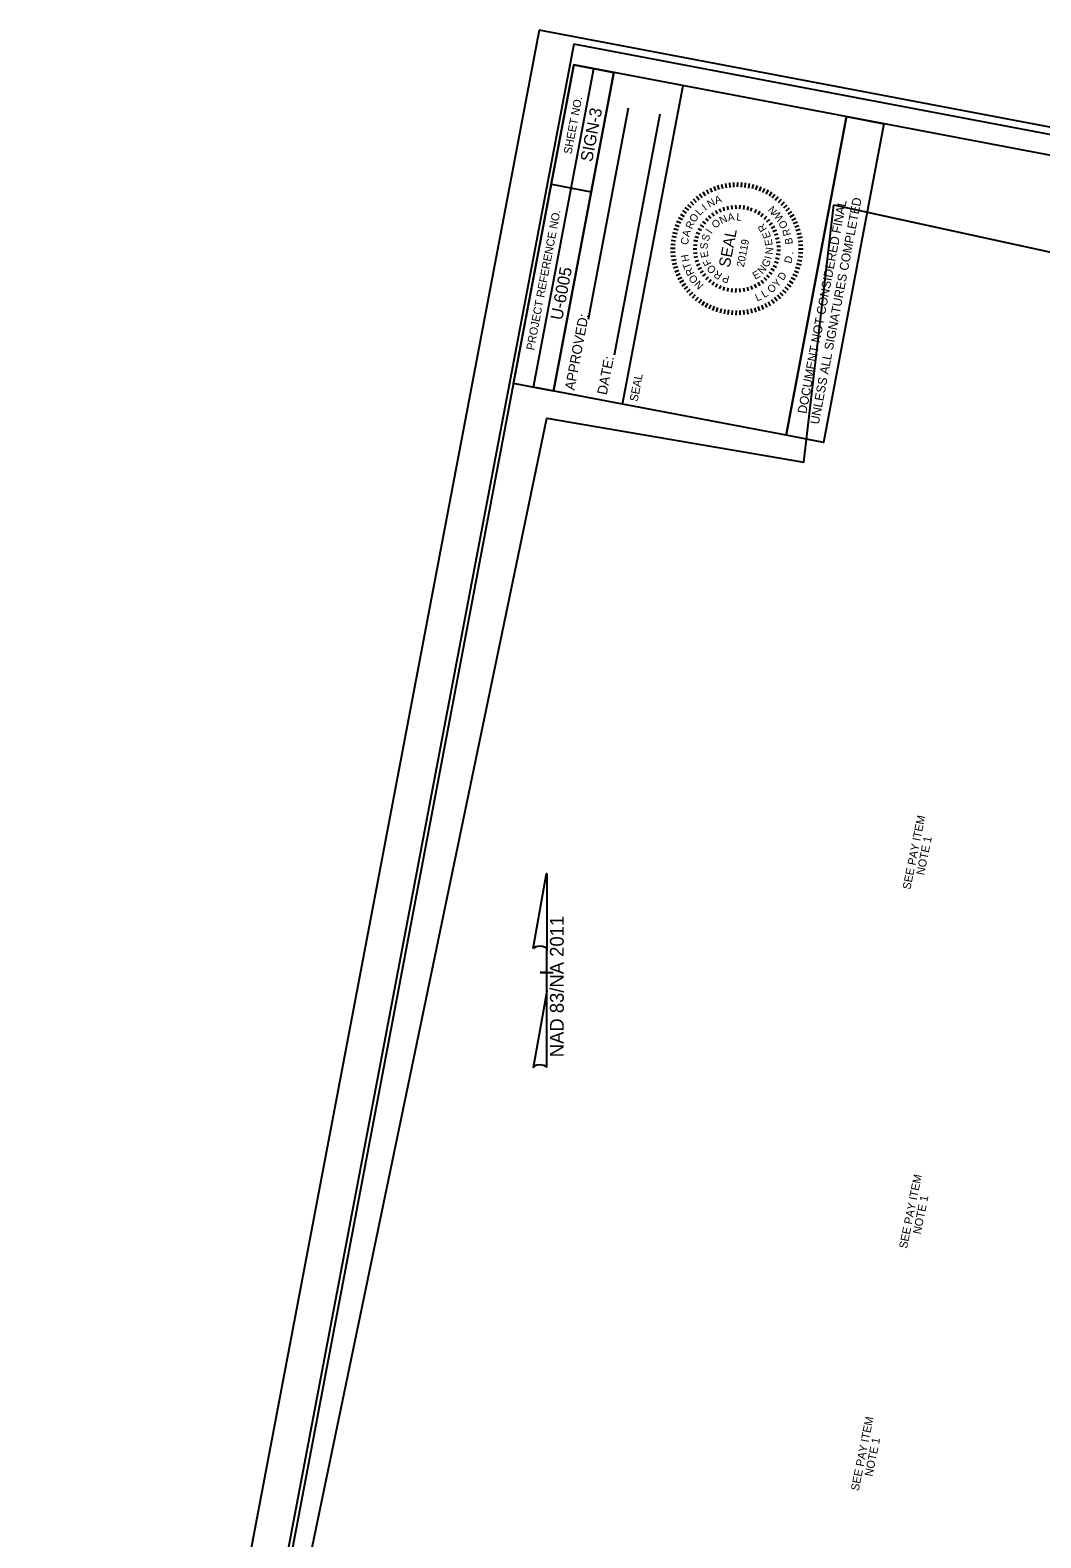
# Model space of a CAD drawing. Extents: x 1615681 to 1617075, y 899309 to 901168.
# Drawn here: x 1615681 to 1616304, y 900239 to 901168 of the extents above; entities that cross this region are included whole.
import ezdxf

# ---------------------------------------------------------------- set-up
doc = ezdxf.new("R2010")
doc.units = 0
for name, color, linetype in [('CTL Primary Horizontal and Vertical CELL', 7, 'Continuous'), ('CTL Primary Horizontal and Vertical Cogo Number', 7, 'Continuous'), ('CTL Secondary Horizontal and Vertical CELL', 7, 'Continuous'), ('CTL Secondary Horizontal and Vertical Cogo Number', 7, 'Continuous'), ('Default', 7, 'Continuous'), ('Exist DTM Crownline Cogo Number', 7, 'Continuous'), ('Exist Roads Curbs Cogo Point CELL', 7, 'Continuous'), ('Exist Roads EOT Cogo Number', 7, 'Continuous'), ('Exist Structure Minor Catch Basin Cogo Number', 7, 'Continuous'), ('Exist Structure Minor Pipes RCP 18 Inch Cogo Number', 7, 'Continuous'), ('Exist Structure Minor Pipes RCP 18 Inch Cogo Point CELL', 7, 'Continuous'), ('Exist Utilities Sanitary Sewer Manhole Cogo Number', 7, 'Continuous')]:
    doc.layers.add(name, color=color, linetype=linetype)

msp = doc.modelspace()

# ---------------------------------------------------------------- linework, layer by layer
at = {"layer": 'CTL Primary Horizontal and Vertical CELL'}
msp.add_lwpolyline([(1616015.87, 901159.82), (1615705.01, 899522.57), (1616741.59, 899325.76), (1617052.45, 900963.01)], close=True, dxfattribs=at)
at = {"layer": 'CTL Primary Horizontal and Vertical Cogo Number'}
msp.add_lwpolyline([(1615994.65, 901168.43), (1615680.53, 899513.99), (1616761.22, 899308.8), (1617075.34, 900963.24)], close=True, dxfattribs=at)
at = {"layer": 'CTL Secondary Horizontal and Vertical CELL'}
for p, q in [((1615991.06, 900948.19), (1616028.37, 901144.73)), ((1616003.34, 900945.86), (1616040.65, 901142.39)), ((1616003.34, 900945.86), (1616040.65, 901142.39)), ((1616002.1, 901073.37), (1616026.66, 901068.71))]:
    msp.add_line(p, q, dxfattribs=at)
for points in [[(1616016.04, 901147.07), (1615736.24, 899673.39), (1616767.81, 899477.53), (1617047.61, 900951.21)], [(1615978.73, 900950.53), (1616016.04, 901147.07), (1616040.65, 901142.39), (1616003.34, 900945.86)]]:
    msp.add_lwpolyline(points, close=True, dxfattribs=at)
at = {"layer": 'Default'}
for p, q in [((1616091.55, 901066), (1616093.25, 901063.8)), ((1616093.55, 901067.45), (1616095.12, 901065.15)), ((1616095.63, 901068.77), (1616097.06, 901066.38)), ((1616097.8, 901069.97), (1616099.07, 901067.5)), ((1616100.02, 901071.03), (1616101.15, 901068.49)), ((1616102.31, 901071.96), (1616103.28, 901069.35)), ((1616104.65, 901072.75), (1616105.46, 901070.08)), ((1616107.04, 901073.39), (1616107.68, 901070.68)), ((1616109.45, 901073.89), (1616109.94, 901071.15)), ((1616111.9, 901074.25), (1616112.21, 901071.47)), ((1616114.36, 901074.45), (1616114.5, 901071.67)), ((1616116.83, 901074.51), (1616116.8, 901071.72)), ((1616119.29, 901074.41), (1616119.1, 901071.63)), ((1616121.75, 901074.17), (1616121.39, 901071.4)), ((1616124.19, 901073.78), (1616123.67, 901071.04)), ((1616126.6, 901073.24), (1616125.91, 901070.54)), ((1616128.97, 901072.56), (1616128.13, 901069.9)), ((1616131.3, 901071.74), (1616130.29, 901069.14)), ((1616133.57, 901070.77), (1616132.41, 901068.24)), ((1616135.79, 901069.67), (1616134.47, 901067.21)), ((1616137.93, 901068.45), (1616136.46, 901066.07)), ((1616139.99, 901067.08), (1616138.39, 901064.8)), ((1616083.05, 901057.11), (1616085.33, 901055.51)), ((1616084.53, 901059.09), (1616086.71, 901057.35)), ((1616086.12, 901060.98), (1616088.19, 901059.11)), ((1616087.83, 901062.76), (1616089.78, 901060.77)), ((1616089.64, 901064.44), (1616091.47, 901062.34)), ((1616103.31, 901057.12), (1616104.45, 901055.1)), ((1616105.64, 901058.28), (1616106.58, 901056.16)), ((1616108.07, 901059.21), (1616108.8, 901057.01)), ((1616110.58, 901059.91), (1616111.09, 901057.65)), ((1616113.15, 901060.36), (1616113.43, 901058.05)), ((1616115.74, 901060.56), (1616115.81, 901058.24)), ((1616118.34, 901060.51), (1616118.18, 901058.19)), ((1616120.93, 901060.21), (1616120.55, 901057.92)), ((1616123.47, 901059.65), (1616122.87, 901057.41)), ((1616125.06, 901056.71), (1616125.87, 901058.89)), ((1616128.35, 901057.83), (1616127.33, 901055.75)), ((1616130.63, 901056.57), (1616129.41, 901054.6)), ((1616141.97, 901065.61), (1616140.23, 901063.43)), ((1616143.85, 901064.01), (1616141.99, 901061.94)), ((1616145.64, 901062.3), (1616143.65, 901060.35)), ((1616147.31, 901060.5), (1616145.21, 901058.66)), ((1616148.88, 901058.58), (1616146.67, 901056.88)), ((1616150.33, 901056.58), (1616148.02, 901055.02)), ((1616078.4, 901048.42), (1616081, 901047.42)), ((1616079.36, 901050.7), (1616081.9, 901049.54)), ((1616080.46, 901052.91), (1616082.92, 901051.6)), ((1616081.69, 901055.05), (1616084.07, 901053.59)), ((1616093.91, 901048.3), (1616095.86, 901047.03)), ((1616095.43, 901050.41), (1616097.25, 901048.97)), ((1616097.15, 901052.37), (1616098.82, 901050.75)), ((1616099.05, 901054.15), (1616100.55, 901052.38)), ((1616101.11, 901055.74), (1616102.44, 901053.83)), ((1616132.77, 901055.1), (1616131.37, 901053.26)), ((1616134.77, 901053.44), (1616133.2, 901051.73)), ((1616136.6, 901051.58), (1616134.87, 901050.03)), ((1616138.23, 901049.56), (1616136.36, 901048.19)), ((1616139.67, 901047.39), (1616137.67, 901046.2)), ((1616151.65, 901054.5), (1616149.26, 901053.08)), ((1616152.85, 901052.34), (1616150.37, 901051.07)), ((1616153.91, 901050.11), (1616151.36, 901048.99)), ((1616154.84, 901047.83), (1616152.23, 901046.85)), ((1616075.97, 901038.87), (1616078.73, 901038.51)), ((1616076.36, 901041.31), (1616079.1, 901040.79)), ((1616076.9, 901043.72), (1616079.6, 901043.04)), ((1616077.58, 901046.1), (1616080.23, 901045.25)), ((1616090.05, 901038.69), (1616092.33, 901038.26)), ((1616092.33, 901038.26), (1616090.05, 901038.69)), ((1616090.66, 901041.23), (1616092.89, 901040.57)), ((1616091.51, 901043.68), (1616093.67, 901042.82)), ((1616092.6, 901046.05), (1616094.66, 901044.98)), ((1616140.89, 901045.09), (1616138.79, 901044.1)), ((1616141.88, 901042.68), (1616139.69, 901041.9)), ((1616142.63, 901040.19), (1616140.38, 901039.62)), ((1616155.63, 901045.48), (1616152.96, 901044.68)), ((1616156.27, 901043.1), (1616153.56, 901042.46)), ((1616156.77, 901040.68), (1616154.02, 901040.2)), ((1616157.12, 901038.24), (1616154.35, 901037.93)), ((1616075.63, 901033.95), (1616078.42, 901033.93)), ((1616075.69, 901031.48), (1616078.47, 901031.63)), ((1616075.73, 901036.42), (1616078.5, 901036.23)), ((1616075.89, 901029.02), (1616078.66, 901029.33)), ((1616089.57, 901033.52), (1616091.89, 901033.52)), ((1616089.68, 901036.11), (1616091.99, 901035.9)), ((1616089.7, 901030.92), (1616092.01, 901031.15)), ((1616090.09, 901028.34), (1616092.37, 901028.8)), ((1616143.15, 901037.63), (1616140.85, 901037.29)), ((1616143.18, 901029.85), (1616140.88, 901030.18)), ((1616143.41, 901035.05), (1616141.09, 901034.92)), ((1616143.42, 901032.44), (1616141.1, 901032.54)), ((1616157.04, 901028.39), (1616154.28, 901028.74)), ((1616157.28, 901030.84), (1616154.51, 901031.03)), ((1616157.33, 901035.78), (1616154.54, 901035.63)), ((1616157.38, 901033.31), (1616154.6, 901033.33)), ((1616076.24, 901026.58), (1616078.99, 901027.06)), ((1616076.75, 901024.16), (1616079.45, 901024.8)), ((1616077.39, 901021.78), (1616080.05, 901022.58)), ((1616078.17, 901019.43), (1616080.79, 901020.4)), ((1616090.72, 901025.82), (1616092.94, 901026.49)), ((1616091.6, 901023.36), (1616093.75, 901024.25)), ((1616092.7, 901021.01), (1616094.76, 901022.1)), ((1616094.03, 901018.77), (1616095.97, 901020.05)), ((1616139.79, 901020.07), (1616137.78, 901021.24)), ((1616138.87, 901023.34), (1616140.98, 901022.36)), ((1616141.96, 901024.8), (1616139.76, 901025.56)), ((1616142.69, 901027.29), (1616140.43, 901027.84)), ((1616154.61, 901018.84), (1616152.01, 901019.84)), ((1616155.43, 901021.16), (1616152.78, 901022.01)), ((1616156.11, 901023.54), (1616153.42, 901024.22)), ((1616156.65, 901025.95), (1616153.92, 901026.47)), ((1616079.1, 901017.15), (1616081.65, 901018.27)), ((1616080.16, 901014.92), (1616082.64, 901016.19)), ((1616081.36, 901012.76), (1616083.76, 901014.18)), ((1616082.69, 901010.68), (1616084.99, 901012.24)), ((1616084.13, 901008.68), (1616086.34, 901010.38)), ((1616095.57, 901016.67), (1616097.38, 901018.13)), ((1616097.31, 901014.73), (1616098.96, 901016.36)), ((1616099.22, 901012.97), (1616100.71, 901014.75)), ((1616101.3, 901011.39), (1616102.61, 901013.31)), ((1616103.51, 901010.03), (1616104.63, 901012.07)), ((1616105.85, 901008.89), (1616106.77, 901011.02)), ((1616108.29, 901007.97), (1616108.99, 901010.18)), ((1616126.16, 901008.48), (1616125.34, 901010.65)), ((1616128.55, 901009.53), (1616127.51, 901011.61)), ((1616130.82, 901010.81), (1616129.59, 901012.77)), ((1616132.95, 901012.29), (1616131.53, 901014.13)), ((1616134.93, 901013.98), (1616133.35, 901015.67)), ((1616136.74, 901015.85), (1616135, 901017.38)), ((1616138.37, 901017.89), (1616136.48, 901019.25)), ((1616149.96, 901010.15), (1616147.68, 901011.75)), ((1616151.32, 901012.21), (1616148.95, 901013.67)), ((1616152.55, 901014.35), (1616150.09, 901015.66)), ((1616153.65, 901016.56), (1616151.12, 901017.72)), ((1616085.7, 901006.76), (1616087.8, 901008.6)), ((1616087.38, 901004.95), (1616089.36, 901006.91)), ((1616089.16, 901003.25), (1616091.03, 901005.32)), ((1616091.05, 901001.65), (1616092.78, 901003.83)), ((1616093.03, 901000.18), (1616094.62, 901002.45)), ((1616095.09, 900998.81), (1616096.55, 901001.19)), ((1616110.8, 901007.3), (1616111.3, 901009.57)), ((1616113.37, 901006.87), (1616113.64, 901009.18)), ((1616115.97, 901006.7), (1616116.01, 901009.02)), ((1616118.57, 901006.77), (1616118.39, 901009.08)), ((1616121.16, 901007.09), (1616120.76, 901009.38)), ((1616123.69, 901007.67), (1616123.07, 901009.9)), ((1616137.38, 900998.49), (1616135.95, 901000.88)), ((1616139.46, 900999.81), (1616137.9, 901002.11)), ((1616141.46, 901001.26), (1616139.76, 901003.46)), ((1616143.37, 901002.82), (1616141.54, 901004.92)), ((1616145.18, 901004.5), (1616143.23, 901006.49)), ((1616146.89, 901006.28), (1616144.82, 901008.15)), ((1616148.49, 901008.17), (1616146.3, 901009.91)), ((1616097.22, 900997.58), (1616098.54, 901000.05)), ((1616099.44, 900996.49), (1616100.6, 900999.02)), ((1616101.71, 900995.52), (1616102.72, 900998.12)), ((1616104.04, 900994.7), (1616104.89, 900997.35)), ((1616106.41, 900994.02), (1616107.1, 900996.72)), ((1616108.82, 900993.48), (1616109.35, 900996.22)), ((1616111.26, 900993.09), (1616111.62, 900995.85)), ((1616113.72, 900992.85), (1616113.91, 900995.63)), ((1616116.18, 900992.75), (1616116.21, 900995.54)), ((1616118.65, 900992.81), (1616118.51, 900995.59)), ((1616121.12, 900993.01), (1616120.8, 900995.79)), ((1616123.56, 900993.37), (1616123.07, 900996.11)), ((1616125.97, 900993.87), (1616125.33, 900996.58)), ((1616128.36, 900994.51), (1616127.55, 900997.18)), ((1616130.7, 900995.3), (1616129.73, 900997.91)), ((1616132.99, 900996.23), (1616131.87, 900998.77)), ((1616135.21, 900997.29), (1616133.94, 900999.76))]:
    msp.add_line(p, q, dxfattribs=at)
at = {"layer": 'Exist DTM Crownline Cogo Number'}
msp.add_lwpolyline([(1616176.29, 901060.7), (1617032.97, 900874.07), (1616753.23, 899510.43), (1615915.8, 899646.19), (1615751.76, 899738.03), (1615999.36, 900929.08), (1616157.93, 900902)], close=True, dxfattribs=at)
at = {"layer": 'Exist Roads Curbs Cogo Point CELL'}
msp.add_line((1616196.89, 901056.22), (1617032.97, 900874.07), dxfattribs=at)
at = {"layer": 'Exist Roads EOT Cogo Number'}
msp.add_lwpolyline([(1616146.85, 900918.61), (1616184.17, 901115.14), (1616207.25, 901110.76), (1616169.93, 900914.22)], close=True, dxfattribs=at)
at = {"layer": 'Exist Structure Minor Catch Basin Cogo Number'}
for p, q in [((1615990.96, 900601.99), (1615999.16, 900648.34)), ((1615999.21, 900648.34), (1615999.16, 900648.34)), ((1615999.21, 900648.34), (1615999.16, 900648.34)), ((1615999.21, 900648.34), (1615999.21, 900600.54)), ((1615999.21, 900575.74), (1615999.21, 900601.94)), ((1615999.21, 900600.54), (1615999.21, 900601.89)), ((1615995.21, 900587.34), (1615995.16, 900587.34)), ((1615998.76, 900587.34), (1615995.21, 900587.34)), ((1615995.26, 900587.34), (1616003.26, 900587.34)), ((1615999.21, 900575.74), (1615990.86, 900528.49)), ((1615999.26, 900528.69), (1615999.21, 900575.74))]:
    msp.add_line(p, q, dxfattribs=at)
for centre, start_param, end_param in [((1615995.1, 900601.49), 0.216388, 2.908219), ((1615995.1, 900528.32), 0.201328, 3.141593)]:
    msp.add_ellipse(centre, major_axis=(4.23, -0.03), ratio=0.461098, start_param=start_param, end_param=end_param, dxfattribs=at)
at = {"layer": 'Exist Structure Minor Pipes RCP 18 Inch Cogo Point CELL'}
for p, q in [((1616024.96, 900990.29), (1616049.7, 901120.58)), ((1616041.04, 900968.22), (1616069.26, 901116.86))]:
    msp.add_line(p, q, dxfattribs=at)
at = {"layer": 'Exist Utilities Sanitary Sewer Manhole Cogo Number'}
for p, q in [((1616046, 900937.76), (1616083.31, 901134.29)), ((1616184.17, 901115.14), (1616146.85, 900918.61)), ((1616037.41, 900939.39), (1615991.06, 900948.19)), ((1616146.85, 900918.61), (1616037.41, 900939.39))]:
    msp.add_line(p, q, dxfattribs=at)

# ---------------------------------------------------------------- texts
at = {"layer": 'CTL Secondary Horizontal and Vertical CELL'}
for s, height, p in [('SHEET NO.', 5, (1616014.48, 901091.69)), ('PROJECT REFERENCE NO.', 5.0001, (1615991.41, 900970.72))]:
    msp.add_text(s, height=height, rotation=79.24937, dxfattribs=at).set_placement(p)
at = {"layer": 'CTL Secondary Horizontal and Vertical Cogo Number'}
for s, p in [('SIGN-3', (1616027.25, 901086.84)), ('U-6005', (1616008.77, 900989.22))]:
    msp.add_text(s, height=7.5, rotation=79.24937, dxfattribs=at).set_placement(p)
at = {"layer": 'Default'}
for s, height, rotation, p in [('A', 4.64, 19.68263, (1616103.7, 901061.15)), ('L', 4.64, 48.3201, (1616093.82, 901053.74)), ('I', 4.64, 38.74462, (1616097.17, 901056.91)), ('N', 4.64, 29.45016, (1616099.76, 901058.78)), ('N', 4.64, 131.37259, (1616141.72, 901057.07)), ('R', 4.64, 64.51319, (1616088.75, 901045.33)), ('O', 4.64, 61.45638, (1616090.91, 901049.49)), ('O', 4.64, 40.92492, (1616103.34, 901045.8)), ('N', 4.64, 25.62867, (1616107.06, 901048.73)), ('A', 4.64, 10.33243, (1616111.27, 901050.51)), ('L', 4.64, 355.03618, (1616116.07, 901051.13)), ('R', 4.64, 123.73042, (1616135.31, 901045.86)), ('W', 4.64, 122.48996, (1616145.58, 901052.37)), ('O', 4.64, 113.60733, (1616148.14, 901047.23)), ('C', 4.64, 76.5225, (1616086.11, 901035.67)), ('A', 4.64, 76.5225, (1616087.15, 901040.63)), ('S', 4.64, 71.51741, (1616098.95, 901037.81)), ('I', 4.64, 56.22117, (1616100.86, 901042.47)), ('SEAL', 6.965, 79.16554, (1616112.11, 901021.77)), ('20119', 4.64, 79.16554, (1616120.85, 901022.03)), ('E', 4.64, 109.95934, (1616137.65, 901040.9)), ('E', 4.64, 99.97346, (1616138.7, 901035.86)), ('R', 4.64, 104.78472, (1616150, 901042.18)), ('B', 4.64, 95.78215, (1616151.06, 901036.52)), ('H', 4.64, 100.23319, (1616087.3, 901026.04)), ('S', 4.64, 86.81366, (1616098.46, 901033.19)), ('E', 4.64, 102.10991, (1616099.2, 901028.61)), ('I', 4.64, 76.95173, (1616137.87, 901026.83)), ('N', 4.64, 84.58139, (1616138.62, 901029.89)), ('D', 4.64, 75.25549, (1616150.03, 901024.22)), ('.', 4.64, 82.99784, (1616151.17, 901029.96)), ('T', 4.64, 109.66514, (1616088.58, 901021.99)), ('R', 4.64, 117.8261, (1616090.55, 901018.44)), ('F', 4.64, 117.40615, (1616101.09, 901024.47)), ('O', 4.64, 132.7024, (1616104.18, 901020.73)), ('R', 4.64, 147.99864, (1616107.93, 901018.15)), ('E', 4.64, 29.23563, (1616127.85, 901014.53)), ('N', 4.64, 50.0907, (1616132.38, 901017.63)), ('G', 4.64, 58.85693, (1616135.38, 901021.68)), ('O', 4.64, 130.88283, (1616092.99, 901014.55)), ('N', 4.64, 132.84226, (1616096.34, 901011.19)), ('P', 4.64, 163.29489, (1616112.31, 901016.59)), ('O', 4.64, 39.81511, (1616137.68, 901005.88)), ('Y', 4.64, 48.4877, (1616141.65, 901009.42)), ('D', 4.64, 57.46018, (1616145.14, 901013.67)), ('L', 4.64, 23.10055, (1616128.98, 901001.03)), ('L', 4.64, 31.17237, (1616133.43, 901003.1)), ('SEE PAY ITEM', 5, 78.45796, (1616223.54, 900638.16)), ('NOTE 1', 5, 78.45796, (1616232.04, 900647.02)), ('SEE PAY ITEM', 5, 78.45796, (1616221.41, 900416.71)), ('NOTE 1', 5, 78.45796, (1616229.91, 900425.57)), ('SEE PAY ITEM', 5, 78.45796, (1616191.65, 900267.35)), ('NOTE 1', 5, 78.45796, (1616200.15, 900276.2))]:
    msp.add_text(s, height=height, rotation=rotation, dxfattribs=at).set_placement(p)
at = {"layer": 'Exist Roads EOT Cogo Number'}
for s, p in [('DOCUMENT NOT CONSIDERED FINAL', (1616159.34, 900931.58)), ('UNLESS ALL SIGNATURES COMPLETED', (1616167.04, 900924.96))]:
    msp.add_text(s, height=5.4984, rotation=79.24937, dxfattribs=at).set_placement(p)
at = {"layer": 'Exist Structure Minor Catch Basin Cogo Number'}
msp.add_text('NAD 83/NA 2011', height=8.5, rotation=90, dxfattribs=at).set_placement((1616009.73, 900535.03))
at = {"layer": 'Exist Structure Minor Pipes RCP 18 Inch Cogo Number'}
for s, p in [('APPROVED:', (1616016.29, 900946.03)), ('DATE:', (1616036.25, 900943.17))]:
    msp.add_text(s, height=6.11, rotation=79.2443, dxfattribs=at).set_placement(p)
at = {"layer": 'Exist Structure Minor Pipes RCP 18 Inch Cogo Point CELL'}
msp.add_text('SEAL', height=5.094, rotation=79.2443, dxfattribs=at).set_placement((1616055.31, 900939.07))

doc.saveas('drawing.dxf')
